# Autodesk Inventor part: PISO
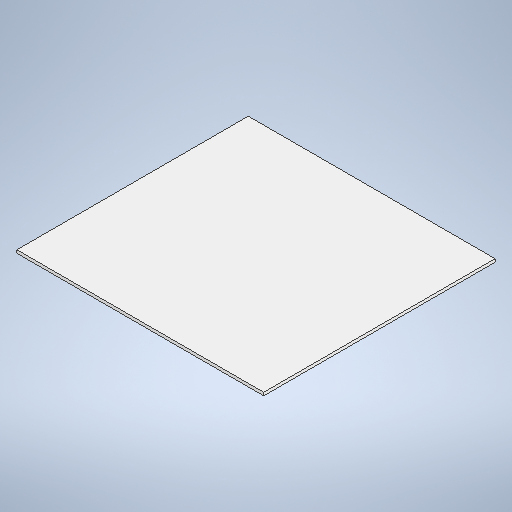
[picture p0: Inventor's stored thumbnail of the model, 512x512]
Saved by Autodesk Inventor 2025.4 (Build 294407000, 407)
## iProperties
Created: 2026-04
Part Number: PISO
Material: PVC-Piping
Document SubType Name: Modeling
Designer: PC
Density: 1.4 g/cm^3
Appearance: White
Author: PC
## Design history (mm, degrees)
sketch "Sketch1"
  geometry: L1 (0, 0)-(320, 0); L2 (320, 0)-(320, -300); L3 (320, -300)-(0, -300); L4 (0, -300)-(0, 0)
  constraints: 8 end point, 2 parallel, 1 horizontal, 1 perpendicular
  dimensions: "d0" = 320 distance of L2.end L3.end; "d1" = 300 distance of L1.end L2.end
extrude "Extrusion1" new body sketch "Sketch1" distance "d2" = 4; taper "d3" = 0 deg
body "Solid1"
